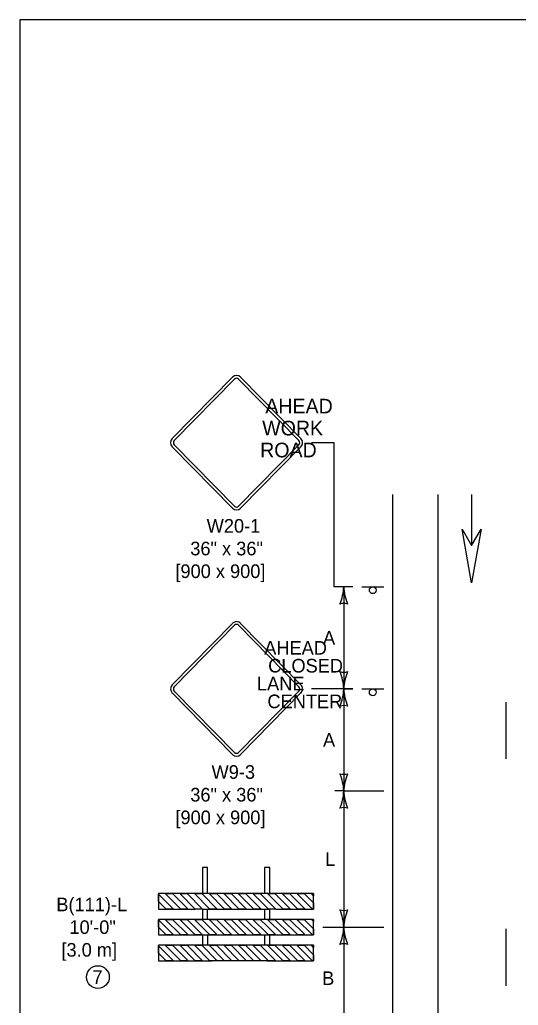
# Model space of a CAD drawing. Extents: x 49991.4 to 50021, y 49987.6 to 50011.4.
# Drawn here: x 50000.336 to 50002.533, y 50006.919 to 50011.263 of the extents above; entities that cross this region are included whole.
import ezdxf

# ---------------------------------------------------------------- set-up
doc = ezdxf.new("R2010")
doc.units = 0
for name, color, linetype in [('Level 1', 7, 'Continuous'), ('Level 2', 7, 'Continuous'), ('Level 3', 7, 'Continuous')]:
    doc.layers.add(name, color=color, linetype=linetype)

msp = doc.modelspace()

# ---------------------------------------------------------------- linework, layer by layer
at = {"layer": 'Level 1'}
for p, q in [((50001.008, 50009.4168), (50001.2732, 50009.6874)), ((50001.0169, 50009.4081), (50001.2821, 50009.6788)), ((50001.3006, 50009.6788), (50001.5658, 50009.4081)), ((50001.3095, 50009.6874), (50001.5747, 50009.4168)), ((50001.2821, 50009.1185), (50001.0169, 50009.3892)), ((50001.5658, 50009.3892), (50001.3006, 50009.1185)), ((50001.2732, 50009.1098), (50001.008, 50009.3805)), ((50001.5747, 50009.3805), (50001.3095, 50009.1098)), ((50001.9802, 50000.6526), (50001.9802, 50009.1708)), ((50002.1802, 50000.6526), (50002.1802, 50009.1708)), ((50002.3277, 50009.1708), (50002.3277, 50008.9449)), ((50002.3279, 50009.1708), (50002.3279, 50008.9449)), ((50001.8442, 50008.7639), (50001.9402, 50008.7639)), ((50001.0081, 50008.332), (50001.2732, 50008.6026)), ((50001.3095, 50008.6026), (50001.5747, 50008.332)), ((50001.0169, 50008.3233), (50001.2821, 50008.594)), ((50001.3007, 50008.594), (50001.5659, 50008.3233)), ((50001.2821, 50008.0337), (50001.0169, 50008.3044)), ((50001.5659, 50008.3044), (50001.3007, 50008.0337)), ((50001.8442, 50008.3139), (50001.9402, 50008.3139)), ((50001.2732, 50008.025), (50001.0081, 50008.2957)), ((50001.5747, 50008.2957), (50001.3095, 50008.025)), ((50002.4803, 50008.0059), (50002.4803, 50008.2559)), ((50000.9473, 50007.4095), (50001.0131, 50007.3436)), ((50000.9473, 50007.4095), (50001.0131, 50007.3436)), ((50000.977, 50007.412), (50001.0454, 50007.3436)), ((50001.0454, 50007.3436), (50000.977, 50007.412)), ((50001.0092, 50007.412), (50001.0776, 50007.3436)), ((50001.0092, 50007.412), (50001.0776, 50007.3436)), ((50001.0414, 50007.412), (50001.1098, 50007.3436)), ((50001.1098, 50007.3436), (50001.0414, 50007.412)), ((50001.0736, 50007.412), (50001.142, 50007.3436)), ((50001.0736, 50007.412), (50001.142, 50007.3436)), ((50001.1059, 50007.412), (50001.1743, 50007.3436)), ((50001.1743, 50007.3436), (50001.1059, 50007.412)), ((50001.1381, 50007.412), (50001.2065, 50007.3436)), ((50001.1381, 50007.412), (50001.2065, 50007.3436)), ((50001.1704, 50007.412), (50001.2388, 50007.3436)), ((50001.2388, 50007.3436), (50001.1704, 50007.412)), ((50001.2026, 50007.412), (50001.271, 50007.3436)), ((50001.2026, 50007.412), (50001.271, 50007.3436)), ((50001.2348, 50007.412), (50001.3032, 50007.3436)), ((50001.3032, 50007.3436), (50001.2348, 50007.412)), ((50001.2671, 50007.412), (50001.3355, 50007.3436)), ((50001.2671, 50007.412), (50001.3355, 50007.3436)), ((50001.2993, 50007.412), (50001.3677, 50007.3436)), ((50001.3677, 50007.3436), (50001.2993, 50007.412)), ((50001.3315, 50007.412), (50001.3999, 50007.3436)), ((50001.3315, 50007.412), (50001.3999, 50007.3436)), ((50001.3638, 50007.412), (50001.4322, 50007.3436)), ((50001.4322, 50007.3436), (50001.3638, 50007.412)), ((50001.396, 50007.412), (50001.4644, 50007.3436)), ((50001.396, 50007.412), (50001.4644, 50007.3436)), ((50001.4283, 50007.412), (50001.4967, 50007.3436)), ((50001.4967, 50007.3436), (50001.4283, 50007.412)), ((50001.4605, 50007.412), (50001.5289, 50007.3436)), ((50001.4605, 50007.412), (50001.5289, 50007.3436)), ((50001.4927, 50007.412), (50001.5611, 50007.3436)), ((50001.5611, 50007.3436), (50001.4927, 50007.412)), ((50001.525, 50007.412), (50001.5934, 50007.3436)), ((50001.525, 50007.412), (50001.5934, 50007.3436)), ((50001.5573, 50007.412), (50001.6257, 50007.3436)), ((50001.6257, 50007.3436), (50001.5573, 50007.412)), ((50001.5895, 50007.412), (50001.6313, 50007.3703)), ((50001.5895, 50007.412), (50001.6313, 50007.3703)), ((50001.6217, 50007.412), (50001.6313, 50007.4025)), ((50001.6313, 50007.4025), (50001.6217, 50007.412)), ((50000.9473, 50007.3773), (50000.9808, 50007.3436)), ((50000.9808, 50007.3436), (50000.9473, 50007.3773)), ((50000.9473, 50007.2955), (50001.0131, 50007.2297)), ((50000.9473, 50007.2955), (50001.0131, 50007.2297)), ((50000.9473, 50007.2633), (50000.9808, 50007.2297)), ((50000.9808, 50007.2297), (50000.9473, 50007.2633)), ((50000.977, 50007.2981), (50001.0454, 50007.2297)), ((50001.0454, 50007.2297), (50000.977, 50007.2981)), ((50001.0092, 50007.2981), (50001.0776, 50007.2297)), ((50001.0092, 50007.2981), (50001.0776, 50007.2297)), ((50001.0414, 50007.2981), (50001.1098, 50007.2297)), ((50001.1098, 50007.2297), (50001.0414, 50007.2981)), ((50001.0736, 50007.2981), (50001.142, 50007.2297)), ((50001.0736, 50007.2981), (50001.142, 50007.2297)), ((50001.1059, 50007.2981), (50001.1743, 50007.2297)), ((50001.1381, 50007.2981), (50001.2065, 50007.2297)), ((50001.1704, 50007.2981), (50001.2388, 50007.2297)), ((50001.2026, 50007.2981), (50001.271, 50007.2297)), ((50001.2348, 50007.2981), (50001.3032, 50007.2297)), ((50001.2671, 50007.2981), (50001.3355, 50007.2297)), ((50001.2993, 50007.2981), (50001.3677, 50007.2297)), ((50001.3315, 50007.2981), (50001.3999, 50007.2297)), ((50001.3638, 50007.2981), (50001.4261, 50007.2358)), ((50001.396, 50007.2981), (50001.4261, 50007.2681)), ((50001.4261, 50007.2681), (50001.4644, 50007.2297)), ((50001.4283, 50007.2981), (50001.4967, 50007.2297)), ((50001.4967, 50007.2297), (50001.4283, 50007.2981)), ((50001.4605, 50007.2981), (50001.5289, 50007.2297)), ((50001.4605, 50007.2981), (50001.5289, 50007.2297)), ((50001.4927, 50007.2981), (50001.5611, 50007.2297)), ((50001.5611, 50007.2297), (50001.4927, 50007.2981)), ((50001.525, 50007.2981), (50001.5934, 50007.2297)), ((50001.525, 50007.2981), (50001.5934, 50007.2297)), ((50001.5573, 50007.2981), (50001.6257, 50007.2297)), ((50001.6257, 50007.2297), (50001.5573, 50007.2981)), ((50001.5895, 50007.2981), (50001.6313, 50007.2564)), ((50001.5895, 50007.2981), (50001.6313, 50007.2564)), ((50001.6217, 50007.2981), (50001.6313, 50007.2886)), ((50001.6313, 50007.2886), (50001.6217, 50007.2981)), ((50002.4803, 50007.0059), (50002.4803, 50007.2559)), ((50001.1639, 50007.2297), (50001.1639, 50007.1841)), ((50001.4147, 50007.2297), (50001.4147, 50007.1841)), ((50001.4261, 50007.2358), (50001.4322, 50007.2297)), ((50000.9473, 50007.1816), (50001.0131, 50007.1157)), ((50000.9473, 50007.1816), (50001.0131, 50007.1157)), ((50000.977, 50007.1841), (50001.0454, 50007.1157)), ((50001.0454, 50007.1157), (50000.977, 50007.1841)), ((50001.0092, 50007.1841), (50001.0776, 50007.1157)), ((50001.0092, 50007.1841), (50001.0776, 50007.1157)), ((50001.0414, 50007.1841), (50001.1098, 50007.1157)), ((50001.1098, 50007.1157), (50001.0414, 50007.1841)), ((50001.0736, 50007.1841), (50001.142, 50007.1157)), ((50001.0736, 50007.1841), (50001.142, 50007.1157)), ((50001.1059, 50007.1841), (50001.1743, 50007.1157)), ((50001.1381, 50007.1841), (50001.2065, 50007.1157)), ((50001.1706, 50007.1841), (50001.239, 50007.1157)), ((50001.2028, 50007.1841), (50001.2712, 50007.1157)), ((50001.235, 50007.1841), (50001.3034, 50007.1157)), ((50001.2672, 50007.1841), (50001.3356, 50007.1157)), ((50001.2994, 50007.1841), (50001.3678, 50007.1157)), ((50001.3316, 50007.1841), (50001.4, 50007.1157)), ((50001.3638, 50007.1841), (50001.4322, 50007.1157)), ((50001.396, 50007.1841), (50001.4644, 50007.1157)), ((50001.4283, 50007.1841), (50001.4967, 50007.1157)), ((50001.4967, 50007.1157), (50001.4283, 50007.1841)), ((50001.4605, 50007.1841), (50001.5289, 50007.1157)), ((50001.4605, 50007.1841), (50001.5289, 50007.1157)), ((50001.4927, 50007.1841), (50001.5611, 50007.1157)), ((50001.5611, 50007.1157), (50001.4927, 50007.1841)), ((50001.525, 50007.1841), (50001.5934, 50007.1157)), ((50001.525, 50007.1841), (50001.5934, 50007.1157)), ((50001.5573, 50007.1841), (50001.6257, 50007.1157)), ((50001.6257, 50007.1157), (50001.5573, 50007.1841)), ((50001.5895, 50007.1841), (50001.6313, 50007.1424)), ((50001.5895, 50007.1841), (50001.6313, 50007.1424)), ((50001.6217, 50007.1841), (50001.6313, 50007.1746)), ((50001.6313, 50007.1746), (50001.6217, 50007.1841)), ((50000.9473, 50007.1493), (50000.9808, 50007.1157)), ((50000.9808, 50007.1157), (50000.9473, 50007.1493)), ((50001.1525, 50007.1157), (50001.1838, 50007.1157)), ((50001.4118, 50007.1157), (50001.1667, 50007.1157)), ((50001.4322, 50007.1157), (50001.3923, 50007.1157))]:
    msp.add_line(p, q, dxfattribs=at)
for points in [[(50008.6146, 50011.2628), (50000.3356, 50011.2628), (50000.3356, 50000.0624), (50008.6146, 50000.0624)], [(50002.3697, 50009.0172), (50002.3279, 50008.7807), (50002.2861, 50009.0172), (50002.3279, 50008.945)]]:
    msp.add_lwpolyline(points, close=True, dxfattribs=at)
for points in [[(50001.1639, 50007.4121), (50001.1639, 50007.5261), (50001.1411, 50007.5261), (50001.1411, 50007.4121)], [(50001.4375, 50007.4121), (50001.4375, 50007.5261), (50001.4147, 50007.5261), (50001.4147, 50007.4121)], [(50001.4644, 50007.3436), (50001.6313, 50007.3436), (50001.6313, 50007.412), (50000.9473, 50007.412), (50000.9473, 50007.3436), (50001.1098, 50007.3436)], [(50000.9473, 50007.3773), (50000.9473, 50007.4095)], [(50000.977, 50007.412), (50001.0092, 50007.412)], [(50001.0414, 50007.412), (50001.0736, 50007.412)], [(50001.1059, 50007.412), (50001.1381, 50007.412)], [(50001.1704, 50007.412), (50001.2026, 50007.412)], [(50001.2348, 50007.412), (50001.2671, 50007.412)], [(50001.2993, 50007.412), (50001.3315, 50007.412)], [(50001.3638, 50007.412), (50001.396, 50007.412)], [(50001.4283, 50007.412), (50001.4605, 50007.412)], [(50001.4927, 50007.412), (50001.525, 50007.412)], [(50001.5573, 50007.412), (50001.5895, 50007.412)], [(50001.6217, 50007.412), (50001.6313, 50007.412), (50001.6313, 50007.4025)], [(50001.0131, 50007.3436), (50000.9808, 50007.3436)], [(50001.0776, 50007.3436), (50001.0454, 50007.3436)], [(50001.142, 50007.3436), (50001.1098, 50007.3436)], [(50001.1411, 50007.3436), (50001.1411, 50007.2981)], [(50001.142, 50007.3436), (50001.4322, 50007.3436)], [(50001.1639, 50007.2981), (50001.1639, 50007.3436)], [(50001.2065, 50007.3436), (50001.1743, 50007.3436)], [(50001.271, 50007.3436), (50001.2388, 50007.3436)], [(50001.3355, 50007.3436), (50001.3032, 50007.3436)], [(50001.3999, 50007.3436), (50001.3677, 50007.3436)], [(50001.4147, 50007.3436), (50001.4147, 50007.2981)], [(50001.4644, 50007.3436), (50001.4322, 50007.3436)], [(50001.4375, 50007.2981), (50001.4375, 50007.3436)], [(50001.5289, 50007.3436), (50001.4967, 50007.3436)], [(50001.5934, 50007.3436), (50001.5611, 50007.3436)], [(50001.6313, 50007.3703), (50001.6313, 50007.3436), (50001.6257, 50007.3436)], [(50001.4261, 50007.2297), (50001.6313, 50007.2297), (50001.6313, 50007.2981), (50000.9473, 50007.2981), (50000.9473, 50007.2297), (50001.4261, 50007.2297)], [(50000.9473, 50007.2633), (50000.9473, 50007.2955)], [(50000.977, 50007.2981), (50001.0092, 50007.2981)], [(50001.0414, 50007.2981), (50001.0736, 50007.2981)], [(50001.2065, 50007.2297), (50001.1743, 50007.2297), (50001.1059, 50007.2981), (50001.1381, 50007.2981), (50001.2065, 50007.2297)], [(50001.271, 50007.2297), (50001.2388, 50007.2297), (50001.1704, 50007.2981), (50001.2026, 50007.2981), (50001.271, 50007.2297)], [(50001.3355, 50007.2297), (50001.3032, 50007.2297), (50001.2348, 50007.2981), (50001.2671, 50007.2981), (50001.3355, 50007.2297)], [(50001.3999, 50007.2297), (50001.3677, 50007.2297), (50001.2993, 50007.2981), (50001.3315, 50007.2981), (50001.3999, 50007.2297)], [(50001.3638, 50007.2981), (50001.396, 50007.2981), (50001.4261, 50007.2681), (50001.4644, 50007.2297), (50001.4375, 50007.2297), (50001.4322, 50007.2297), (50001.4261, 50007.2358), (50001.3638, 50007.2981)], [(50001.4283, 50007.2981), (50001.4605, 50007.2981)], [(50001.4927, 50007.2981), (50001.525, 50007.2981)], [(50001.5573, 50007.2981), (50001.5895, 50007.2981)], [(50001.6217, 50007.2981), (50001.6313, 50007.2981), (50001.6313, 50007.2886)], [(50001.6313, 50007.2564), (50001.6313, 50007.2297), (50001.6257, 50007.2297)], [(50001.0131, 50007.2297), (50000.9808, 50007.2297)], [(50001.0776, 50007.2297), (50001.0454, 50007.2297)], [(50001.142, 50007.2297), (50001.1098, 50007.2297)], [(50001.1411, 50007.2297), (50001.1411, 50007.1841)], [(50001.4375, 50007.1841), (50001.4375, 50007.2297)], [(50001.5289, 50007.2297), (50001.4967, 50007.2297)], [(50001.5934, 50007.2297), (50001.5611, 50007.2297)], [(50001.4261, 50007.1841), (50000.9473, 50007.1841), (50000.9473, 50007.1157), (50001.1525, 50007.1157)], [(50000.9473, 50007.1493), (50000.9473, 50007.1816)], [(50000.977, 50007.1841), (50001.0092, 50007.1841)], [(50001.0414, 50007.1841), (50001.0736, 50007.1841)], [(50001.2065, 50007.1157), (50001.1838, 50007.1157), (50001.1743, 50007.1157), (50001.1059, 50007.1841), (50001.1381, 50007.1841), (50001.2065, 50007.1157)], [(50001.2712, 50007.1157), (50001.239, 50007.1157), (50001.1706, 50007.1841), (50001.2028, 50007.1841), (50001.2712, 50007.1157)], [(50001.3356, 50007.1157), (50001.3034, 50007.1157), (50001.235, 50007.1841), (50001.2672, 50007.1841), (50001.3356, 50007.1157)], [(50001.4, 50007.1157), (50001.3923, 50007.1157), (50001.3678, 50007.1157), (50001.2994, 50007.1841), (50001.3316, 50007.1841), (50001.4, 50007.1157)], [(50001.3638, 50007.1841), (50001.396, 50007.1841), (50001.4644, 50007.1157), (50001.4322, 50007.1157), (50001.3638, 50007.1841)], [(50001.4261, 50007.1157), (50001.6313, 50007.1157), (50001.6313, 50007.1841), (50001.4261, 50007.1841)], [(50001.4283, 50007.1841), (50001.4605, 50007.1841)], [(50001.4927, 50007.1841), (50001.525, 50007.1841)], [(50001.5573, 50007.1841), (50001.5895, 50007.1841)], [(50001.6217, 50007.1841), (50001.6313, 50007.1841), (50001.6313, 50007.1746)], [(50001.6313, 50007.1424), (50001.6313, 50007.1157), (50001.6257, 50007.1157)], [(50001.0131, 50007.1157), (50000.9808, 50007.1157)], [(50001.0776, 50007.1157), (50001.0454, 50007.1157)], [(50001.142, 50007.1157), (50001.1098, 50007.1157)], [(50001.5289, 50007.1157), (50001.4967, 50007.1157)], [(50001.5934, 50007.1157), (50001.5611, 50007.1157)]]:
    msp.add_lwpolyline(points, dxfattribs=at)
for centre in [(50001.8922, 50008.7487), (50001.8922, 50008.2987)]:
    msp.add_circle(centre, 0.0152, dxfattribs=at)
for centre, major_axis, ratio, start_param, end_param in [((50001.2914, 50009.6693), (0, 0.0258), 0.98963, 5.497795, 7.068583), ((50001.2914, 50009.6693), (0, 0.0134), 0.98, 5.497795, 7.068583), ((50001.0261, 50009.3987), (0, -0.0258), 0.98963, 3.926991, 5.497787), ((50001.0261, 50009.3987), (0, -0.0134), 0.98, 3.926991, 5.497787), ((50001.5566, 50009.3987), (0, -0.0134), 0.98, 0.785394, 2.356194), ((50001.5566, 50009.3987), (0, -0.0258), 0.98963, 0.785394, 2.356194), ((50001.2914, 50009.128), (0, -0.0258), 0.98963, 5.497787, 7.068583), ((50001.2914, 50009.128), (0, -0.0134), 0.98, 5.497787, 7.068583), ((50001.2914, 50008.5845), (0, 0.0258), 0.98963, 5.497795, 7.068583), ((50001.2914, 50008.5845), (0, 0.0134), 0.98, 5.497795, 7.068583), ((50001.0262, 50008.3139), (0, -0.0258), 0.98963, 3.926991, 5.497787), ((50001.0262, 50008.3139), (0, -0.0134), 0.98, 3.926991, 5.497787), ((50001.5566, 50008.3139), (0, -0.0134), 0.98, 0.785394, 2.356194), ((50001.5566, 50008.3139), (0, -0.0258), 0.98963, 0.785394, 2.356194), ((50001.2914, 50008.0432), (0, -0.0258), 0.98963, 5.497787, 7.068583), ((50001.2914, 50008.0432), (0, -0.0134), 0.98, 5.497787, 7.068583)]:
    msp.add_ellipse(centre, major_axis=major_axis, ratio=ratio, start_param=start_param, end_param=end_param, dxfattribs=at)
at = {"layer": 'Level 2'}
msp.add_circle((50000.6803, 50007.0437), 0.0501, dxfattribs=at)
at = {"layer": 'Level 3'}
for p, q in [((50001.7216, 50009.3987), (50001.6221, 50009.3987)), ((50001.7216, 50008.7639), (50001.7216, 50009.3987)), ((50001.8042, 50008.7639), (50001.7216, 50008.7639)), ((50001.7642, 50008.7639), (50001.7642, 50008.3139)), ((50001.8042, 50008.3139), (50001.6221, 50008.3139)), ((50001.7642, 50008.3139), (50001.7242, 50008.3139)), ((50001.7642, 50008.3139), (50001.7642, 50007.8639)), ((50001.7642, 50008.3139), (50001.8042, 50008.3139)), ((50001.7642, 50007.8639), (50001.7242, 50007.8639)), ((50001.7642, 50007.8639), (50001.9402, 50007.8639)), ((50001.7642, 50007.8639), (50001.7642, 50007.2639)), ((50001.6713, 50007.2639), (50001.9402, 50007.2639)), ((50001.7642, 50007.2639), (50001.7642, 50006.8139))]:
    msp.add_line(p, q, dxfattribs=at)
for centre, radius, start, end in [((50001.5421, 50008.773), 0.2223, 337.456, 357.6395), ((50001.9969, 50008.7754), 0.233, 182.8273, 202.0772), ((50001.7642, 50008.6357), 0.0548, 72.1388, 107.8612), ((50001.7642, 50008.4421), 0.0548, 252.1388, 287.8612), ((50001.5315, 50008.3024), 0.233, 2.8273, 22.0772), ((50001.9863, 50008.3047), 0.2223, 157.456, 177.6395), ((50001.5421, 50008.323), 0.2223, 337.456, 357.6395), ((50001.9969, 50008.3254), 0.233, 182.8273, 202.0772), ((50001.7642, 50008.1857), 0.0548, 72.1388, 107.8612), ((50001.7642, 50007.9921), 0.0548, 252.1388, 287.8612), ((50001.5315, 50007.8524), 0.233, 2.8273, 22.0772), ((50001.9863, 50007.8547), 0.2223, 157.456, 177.6395), ((50001.5421, 50007.873), 0.2223, 337.456, 357.6395), ((50001.9969, 50007.8754), 0.233, 182.8273, 202.0772), ((50001.7642, 50007.7357), 0.0548, 72.1388, 107.8612), ((50001.7642, 50007.3921), 0.0548, 252.1388, 287.8612), ((50001.5315, 50007.2524), 0.233, 2.8273, 22.0772), ((50001.9863, 50007.2547), 0.2223, 157.456, 177.6395), ((50001.5421, 50007.273), 0.2223, 337.456, 357.6395), ((50001.9969, 50007.2754), 0.233, 182.8273, 202.0772), ((50001.7642, 50007.1357), 0.0548, 72.1388, 107.8612)]:
    msp.add_arc(centre, radius, start, end, dxfattribs=at)

# ---------------------------------------------------------------- texts
at = {"layer": 'Level 1'}
for s, height, p in [('AHEAD', 0.06453, (50001.4183, 50009.5277)), ('WORK', 0.06453, (50001.4046, 50009.4309)), ('ROAD', 0.06453, (50001.3955, 50009.3342)), ('AHEAD', 0.06, (50001.4135, 50008.4646)), ('CLOSED', 0.06, (50001.4309, 50008.386)), ('LANE', 0.06, (50001.3815, 50008.3073)), ('CENTER', 0.06, (50001.4276, 50008.2287))]:
    msp.add_text(s, height=height, rotation=360, dxfattribs=at).set_placement(p)
at = {"layer": 'Level 2'}
for s, p in [('W20-1', (50001.1598, 50009.0023)), ('36" x 36"', (50001.0875, 50008.9023)), ('[900 x 900]', (50001.0219, 50008.8023)), ('W9-3', (50001.1813, 50007.9175)), ('36" x 36"', (50001.0875, 50007.8175)), ('[900 x 900]', (50001.022, 50007.7175)), ('L', (50001.6818, 50007.5339)), ('B(111)-L', (50000.497, 50007.3338)), ('10\'-0"', (50000.5548, 50007.2338)), ('[3.0 m]', (50000.5196, 50007.1338)), ('7', (50000.6564, 50007.0137)), ('B', (50001.6687, 50007.0089))]:
    msp.add_text(s, height=0.06, dxfattribs=at).set_placement(p)
for p in [(50001.6727, 50008.5089), (50001.6727, 50008.0589)]:
    msp.add_text('A', height=0.06, rotation=0, dxfattribs=at).set_placement(p)

doc.saveas('drawing.dxf')
